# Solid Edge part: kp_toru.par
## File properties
Author: Georg
Template: Iso Metric Part.par
Last saved by: Georg
Revision: 3
Application: Solid Edge
Accuracy: 0,990
Face Style: Model Default
Fill Style: Normal
Coef. of Thermal Exp: 0.0
Thermal Conductivity: 0.0
Specific Heat: 0.0
Modulus of Elasticity: 0.0
Poisson's Ratio: 0.0
Yield Stress: 0.0
Ultimate Stress: 0.0
Elongation: 0.0
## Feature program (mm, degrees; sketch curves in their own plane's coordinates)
sketch for "ExtrudedProtrusion_1" #1 plane through (0, 0, -170) normal (0, 0, 1) x-axis (1, 0, 0)
  line (-62.5, 4420.2777) -> (-62.5, 4370.2777)
  line (-37.5, 4370.2777) -> (-62.5, 4370.2777)
  line (-37.5, 4370.2777) -> (-37.5, 4420.2777)
  line (-37.5, 4420.2777) -> (-37.5, 4470.2777)
  line (-37.5, 4470.2777) -> (-62.5, 4470.2777)
  line (-62.5, 4470.2777) -> (-62.5, 4420.2777)
sketch for "ExtrudedProtrusion_1" #2 plane through (0, 0, -170) normal (0, 0, 1) x-axis (1, 0, 0)
  line (-70, 4362.7777) -> (-30, 4362.7777)
  line (-30, 4362.7777) -> (-30, 4477.7777)
  line (-30, 4477.7777) -> (-70, 4477.7777)
  line (-70, 4477.7777) -> (-70, 4362.7777)
sketch for "ExtrudedProtrusion_1" #3 plane through (0, 0, -170) normal (0, 0, 1) x-axis (1, 0, 0)
  line (70, 4362.7777) -> (70, 4477.7777)
  line (70, 4477.7777) -> (30, 4477.7777)
  line (30, 4477.7777) -> (30, 4362.7777)
  line (30, 4362.7777) -> (70, 4362.7777)
sketch for "ExtrudedProtrusion_1" #4 plane through (0, 0, -170) normal (0, 0, 1) x-axis (1, 0, 0)
  line (62.5, 4370.2777) -> (62.5, 4420.2777)
  line (62.5, 4420.2777) -> (62.5, 4470.2777)
  line (62.5, 4470.2777) -> (37.5, 4470.2777)
  line (37.5, 4470.2777) -> (37.5, 4420.2777)
  line (37.5, 4420.2777) -> (37.5, 4370.2777)
  line (62.5, 4370.2777) -> (37.5, 4370.2777)
extrude "ExtrudedProtrusion_1" add finite 150 along -normal
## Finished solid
Body 1: solid body, 20 faces, 48 edges, 32 vertices, 2 separate solids.
  Faces by surface: plane 20
  Edges by curve: line 48
Bounding box of the edges (mm): 140.000 x 115.000 x 150.000, from (-70, 4362.7777, -320) to (70, 4477.7777, -170).
Planar faces by outward normal: +x 4, +y 4, +z 2, -x 4, -y 4, -z 2
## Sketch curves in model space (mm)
line (-62.5, 4420.2777, -170) -> (-62.5, 4370.2777, -170)
line (-37.5, 4370.2777, -170) -> (-62.5, 4370.2777, -170)
line (-37.5, 4370.2777, -170) -> (-37.5, 4420.2777, -170)
line (-37.5, 4420.2777, -170) -> (-37.5, 4470.2777, -170)
line (-37.5, 4470.2777, -170) -> (-62.5, 4470.2777, -170)
line (-62.5, 4470.2777, -170) -> (-62.5, 4420.2777, -170)
line (-30, 4362.7777, -170) -> (-30, 4477.7777, -170)
line (-30, 4477.7777, -170) -> (-70, 4477.7777, -170)
line (-70, 4477.7777, -170) -> (-70, 4362.7777, -170)
line (-70, 4362.7777, -170) -> (-30, 4362.7777, -170)
line (70, 4362.7777, -170) -> (70, 4477.7777, -170)
line (70, 4477.7777, -170) -> (30, 4477.7777, -170)
line (30, 4477.7777, -170) -> (30, 4362.7777, -170)
line (30, 4362.7777, -170) -> (70, 4362.7777, -170)
line (37.5, 4420.2777, -170) -> (37.5, 4370.2777, -170)
line (62.5, 4370.2777, -170) -> (37.5, 4370.2777, -170)
line (62.5, 4370.2777, -170) -> (62.5, 4420.2777, -170)
line (62.5, 4420.2777, -170) -> (62.5, 4470.2777, -170)
line (62.5, 4470.2777, -170) -> (37.5, 4470.2777, -170)
line (37.5, 4470.2777, -170) -> (37.5, 4420.2777, -170)
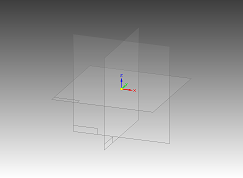
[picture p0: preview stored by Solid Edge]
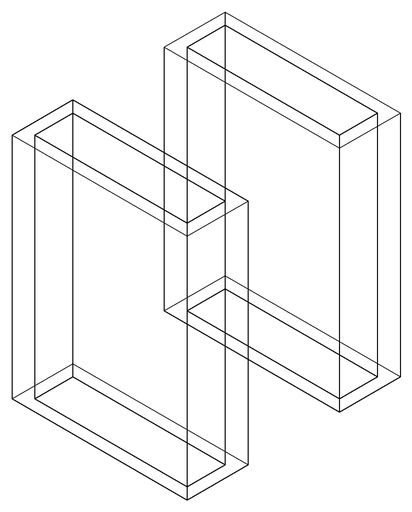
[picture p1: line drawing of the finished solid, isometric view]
